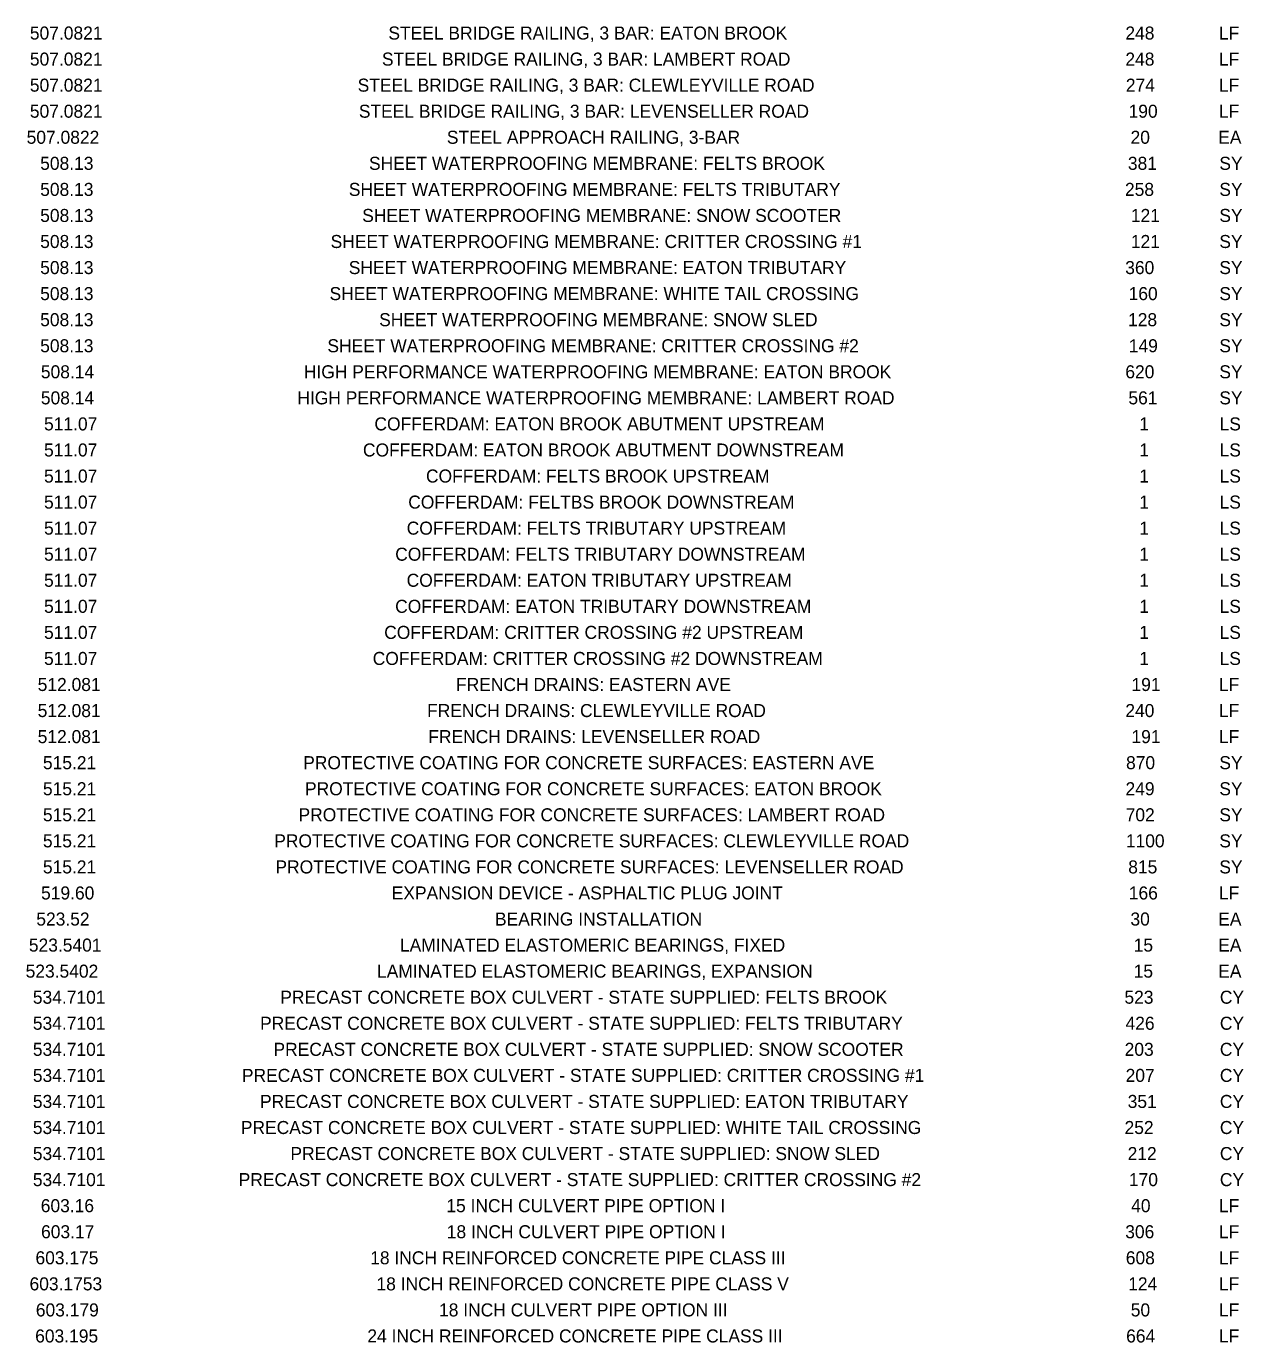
# Model space of a CAD drawing. Extents: x -18.7 to 5.6, y -2.7 to 4.
# Drawn here: x -18.677 to -17.757, y 1.164 to 2.159 of the extents above; entities that cross this region are included whole.
import ezdxf

# ---------------------------------------------------------------- set-up
doc = ezdxf.new("R2010")
doc.units = 0
doc.layers.add('ANNOTATION', color=7, linetype='Continuous')

msp = doc.modelspace()

# ---------------------------------------------------------------- texts
at = {"layer": 'ANNOTATION'}
for s, height, p in [('507.0821', 0.009843, (-18.674, 2.14859)), ('STEEL BRIDGE RAILING, 3 BAR: EATON BROOK', 0.009843, (-18.40311, 2.14859)), ('248', 0.009843, (-17.84626, 2.14859)), ('LF', 0.009843, (-17.77549, 2.14859)), ('507.0821', 0.009843, (-18.674, 2.1289)), ('STEEL BRIDGE RAILING, 3 BAR: LAMBERT ROAD', 0.009843, (-18.408, 2.1289)), ('248', 0.009843, (-17.84626, 2.1289)), ('LF', 0.009843, (-17.77549, 2.1289)), ('507.0821', 0.009843, (-18.674, 2.10921)), ('STEEL BRIDGE RAILING, 3 BAR: CLEWLEYVILLE ROAD', 0.009843, (-18.42633, 2.10921)), ('274', 0.009843, (-17.84592, 2.10921)), ('LF', 0.009843, (-17.77549, 2.10921)), ('507.0821', 0.009843, (-18.674, 2.08953)), ('STEEL BRIDGE RAILING, 3 BAR: LEVENSELLER ROAD', 0.009843, (-18.42543, 2.08953)), ('190', 0.009843, (-17.84382, 2.08953)), ('LF', 0.009843, (-17.77549, 2.08953)), ('507.0822', 0.009843, (-18.67644, 2.06984)), ('STEEL APPROACH RAILING, 3-BAR', 0.009843, (-18.35896, 2.06984)), ('20', 0.009843, (-17.84235, 2.06984)), ('EA', 0.009843, (-17.77611, 2.06984)), ('508.13', 0.009843, (-18.66621, 2.05016)), ('SHEET WATERPROOFING MEMBRANE: FELTS BROOK', 0.009843, (-18.41775, 2.05016)), ('381', 0.009843, (-17.84436, 2.05016)), ('SY', 0.009843, (-17.77526, 2.05016)), ('508.13', 0.009843, (-18.66621, 2.03047)), ('SHEET WATERPROOFING MEMBRANE: FELTS TRIBUTARY', 0.009843, (-18.43302, 2.03047)), ('258', 0.009843, (-17.84657, 2.03047)), ('SY', 0.009843, (-17.77526, 2.03047)), ('508.13', 0.009843, (-18.66621, 2.01078)), ('SHEET WATERPROOFING MEMBRANE: SNOW SCOOTER', 0.009843, (-18.4229, 2.01078)), ('121', 0.009843, (-17.84212, 2.01078)), ('SY', 0.009843, (-17.77526, 2.01078)), ('508.13', 0.009843, (-18.66621, 1.9911)), ('SHEET WATERPROOFING MEMBRANE: CRITTER CROSSING #1', 0.009843, (-18.44676, 1.9911)), ('121', 0.009843, (-17.84212, 1.9911)), ('SY', 0.009843, (-17.77526, 1.9911)), ('508.13', 0.009843, (-18.66621, 1.97141)), ('SHEET WATERPROOFING MEMBRANE: EATON TRIBUTARY', 0.009843, (-18.43306, 1.97141)), ('360', 0.009843, (-17.84638, 1.97141)), ('SY', 0.009843, (-17.77526, 1.97141)), ('508.13', 0.009843, (-18.66621, 1.95173)), ('SHEET WATERPROOFING MEMBRANE: WHITE TAIL CROSSING', 0.009843, (-18.44756, 1.95173)), ('160', 0.009843, (-17.84382, 1.95173)), ('SY', 0.009843, (-17.77526, 1.95173)), ('508.13', 0.009843, (-18.66621, 1.93204)), ('SHEET WATERPROOFING MEMBRANE: SNOW SLED', 0.009843, (-18.41009, 1.93204)), ('128', 0.009843, (-17.84425, 1.93204)), ('SY', 0.009843, (-17.77526, 1.93204)), ('508.13', 0.009843, (-18.66621, 1.91235)), ('SHEET WATERPROOFING MEMBRANE: CRITTER CROSSING #2', 0.009843, (-18.4492, 1.91235)), ('149', 0.009843, (-17.84367, 1.91235)), ('SY', 0.009843, (-17.77526, 1.91235)), ('508.14', 0.009843, (-18.6657, 1.89267)), ('HIGH PERFORMANCE WATERPROOFING MEMBRANE: EATON BROOK', 0.009843, (-18.467, 1.89267)), ('620', 0.009843, (-17.8463, 1.89267)), ('SY', 0.009843, (-17.77526, 1.89267)), ('508.14', 0.009843, (-18.6657, 1.87298)), ('HIGH PERFORMANCE WATERPROOFING MEMBRANE: LAMBERT ROAD', 0.009843, (-18.47189, 1.87298)), ('561', 0.009843, (-17.84398, 1.87298)), ('SY', 0.009843, (-17.77526, 1.87298)), ('511.07', 0.009843, (-18.6633, 1.8533)), ('COFFERDAM: EATON BROOK ABUTMENT UPSTREAM', 0.009843, (-18.41366, 1.8533)), ('1', 0.00984, (-17.83576, 1.8533)), ('LS', 0.009843, (-17.77506, 1.8533)), ('511.07', 0.009843, (-18.6633, 1.83361)), ('COFFERDAM: EATON BROOK ABUTMENT DOWNSTREAM', 0.009843, (-18.42234, 1.83361)), ('1', 0.00984, (-17.83576, 1.83361)), ('LS', 0.009843, (-17.77506, 1.83361)), ('511.07', 0.009843, (-18.6633, 1.81392)), ('COFFERDAM: FELTS BROOK UPSTREAM', 0.009843, (-18.37471, 1.81392)), ('1', 0.00984, (-17.83576, 1.81392)), ('LS', 0.009843, (-17.77506, 1.81392)), ('511.07', 0.009843, (-18.6633, 1.79424)), ('COFFERDAM: FELTBS BROOK DOWNSTREAM', 0.009843, (-18.38812, 1.79424)), ('1', 0.00984, (-17.83576, 1.79424)), ('LS', 0.009843, (-17.77506, 1.79424)), ('511.07', 0.009843, (-18.6633, 1.77455)), ('COFFERDAM: FELTS TRIBUTARY UPSTREAM', 0.009843, (-18.38928, 1.77455)), ('1', 0.00984, (-17.83576, 1.77455)), ('LS', 0.009843, (-17.77506, 1.77455)), ('511.07', 0.009843, (-18.6633, 1.75487)), ('COFFERDAM: FELTS TRIBUTARY DOWNSTREAM', 0.009843, (-18.39796, 1.75487)), ('1', 0.00984, (-17.83576, 1.75487)), ('LS', 0.009843, (-17.77506, 1.75487)), ('511.07', 0.009843, (-18.6633, 1.73518)), ('COFFERDAM: EATON TRIBUTARY UPSTREAM', 0.009843, (-18.38932, 1.73518)), ('1', 0.00984, (-17.83576, 1.73518)), ('LS', 0.009843, (-17.77506, 1.73518)), ('511.07', 0.009843, (-18.6633, 1.71549)), ('COFFERDAM: EATON TRIBUTARY DOWNSTREAM', 0.009843, (-18.398, 1.71549)), ('1', 0.00984, (-17.83576, 1.71549)), ('LS', 0.009843, (-17.77506, 1.71549)), ('511.07', 0.009843, (-18.6633, 1.69581)), ('COFFERDAM: CRITTER CROSSING #2 UPSTREAM', 0.009843, (-18.40627, 1.69581)), ('1', 0.00984, (-17.83576, 1.69581)), ('LS', 0.009843, (-17.77506, 1.69581)), ('511.07', 0.009843, (-18.6633, 1.67612)), ('COFFERDAM: CRITTER CROSSING #2 DOWNSTREAM', 0.009843, (-18.41496, 1.67612)), ('1', 0.00984, (-17.83576, 1.67612)), ('LS', 0.009843, (-17.77506, 1.67612)), ('512.081', 0.009843, (-18.6681, 1.65644)), ('FRENCH DRAINS: EASTERN AVE', 0.009843, (-18.35201, 1.65644)), ('191', 0.009843, (-17.84165, 1.65644)), ('LF', 0.009843, (-17.77549, 1.65644)), ('512.081', 0.009843, (-18.6681, 1.63675)), ('FRENCH DRAINS: CLEWLEYVILLE ROAD', 0.009843, (-18.37387, 1.63675)), ('240', 0.009843, (-17.8463, 1.63675)), ('LF', 0.009843, (-17.77549, 1.63675)), ('512.081', 0.009843, (-18.6681, 1.61706)), ('FRENCH DRAINS: LEVENSELLER ROAD', 0.009843, (-18.37297, 1.61706)), ('191', 0.009843, (-17.84165, 1.61706)), ('LF', 0.009843, (-17.77549, 1.61706)), ('515.21', 0.009843, (-18.66415, 1.59738)), ('PROTECTIVE COATING FOR CONCRETE SURFACES: EASTERN AVE', 0.009843, (-18.46749, 1.59738)), ('870', 0.009843, (-17.84576, 1.59738)), ('SY', 0.009843, (-17.77526, 1.59738)), ('515.21', 0.009843, (-18.66415, 1.57769)), ('PROTECTIVE COATING FOR CONCRETE SURFACES: EATON BROOK', 0.009843, (-18.46613, 1.57769)), ('249', 0.009843, (-17.84615, 1.57769)), ('SY', 0.009843, (-17.77526, 1.57769)), ('515.21', 0.009843, (-18.66415, 1.55801)), ('PROTECTIVE COATING FOR CONCRETE SURFACES: LAMBERT ROAD', 0.009843, (-18.47102, 1.55801)), ('702', 0.009843, (-17.84603, 1.55801)), ('SY', 0.009843, (-17.77526, 1.55801)), ('515.21', 0.009843, (-18.66415, 1.53832)), ('PROTECTIVE COATING FOR CONCRETE SURFACES: CLEWLEYVILLE ROAD', 0.009843, (-18.48935, 1.53832)), ('1100', 0.009843, (-17.84591, 1.53832)), ('SY', 0.009843, (-17.77526, 1.53832)), ('515.21', 0.009843, (-18.66415, 1.51863)), ('PROTECTIVE COATING FOR CONCRETE SURFACES: LEVENSELLER ROAD', 0.009843, (-18.48845, 1.51863)), ('815', 0.009843, (-17.84409, 1.51863)), ('SY', 0.009843, (-17.77526, 1.51863)), ('519.60', 0.009843, (-18.66555, 1.49895)), ('EXPANSION DEVICE - ASPHALTIC PLUG JOINT', 0.009843, (-18.4006, 1.49895)), ('166', 0.009843, (-17.84367, 1.49895)), ('LF', 0.009843, (-17.77549, 1.49895)), ('523.52', 0.009843, (-18.66915, 1.47926)), ('BEARING INSTALLATION', 0.009843, (-18.32257, 1.47926)), ('30', 0.009843, (-17.84243, 1.47926)), ('EA', 0.009843, (-17.77611, 1.47926)), ('523.5401', 0.009843, (-18.67477, 1.45958)), ('LAMINATED ELASTOMERIC BEARINGS, FIXED', 0.009843, (-18.39438, 1.45958)), ('15', 0.009843, (-17.83999, 1.45958)), ('EA', 0.009843, (-17.77611, 1.45958)), ('523.5402', 0.009843, (-18.67721, 1.43989)), ('LAMINATED ELASTOMERIC BEARINGS, EXPANSION', 0.009843, (-18.4117, 1.43989)), ('15', 0.009843, (-17.83999, 1.43989)), ('EA', 0.009843, (-17.77611, 1.43989)), ('534.7101', 0.009843, (-18.67175, 1.4202)), ('PRECAST CONCRETE BOX CULVERT - STATE SUPPLIED: FELTS BROOK', 0.009843, (-18.4848, 1.4202)), ('523', 0.009843, (-17.84696, 1.4202)), ('CY', 0.009843, (-17.77487, 1.4202)), ('534.7101', 0.009843, (-18.67175, 1.40052)), ('PRECAST CONCRETE BOX CULVERT - STATE SUPPLIED: FELTS TRIBUTARY', 0.009843, (-18.50006, 1.40052)), ('426', 0.009843, (-17.84615, 1.40052)), ('CY', 0.009843, (-17.77487, 1.40052)), ('534.7101', 0.009843, (-18.67175, 1.38083)), ('PRECAST CONCRETE BOX CULVERT - STATE SUPPLIED: SNOW SCOOTER', 0.009843, (-18.48995, 1.38083)), ('203', 0.009843, (-17.84681, 1.38083)), ('CY', 0.009843, (-17.77487, 1.38083)), ('534.7101', 0.009843, (-18.67175, 1.36115)), ('PRECAST CONCRETE BOX CULVERT - STATE SUPPLIED: CRITTER CROSSING #1', 0.009843, (-18.51381, 1.36115)), ('207', 0.009843, (-17.84607, 1.36115)), ('CY', 0.009843, (-17.77487, 1.36115)), ('534.7101', 0.009843, (-18.67175, 1.34146)), ('PRECAST CONCRETE BOX CULVERT - STATE SUPPLIED: EATON TRIBUTARY', 0.009843, (-18.50011, 1.34146)), ('351', 0.009843, (-17.84452, 1.34146)), ('CY', 0.009843, (-17.77487, 1.34146)), ('534.7101', 0.009843, (-18.67175, 1.32177)), ('PRECAST CONCRETE BOX CULVERT - STATE SUPPLIED: WHITE TAIL CROSSING', 0.009843, (-18.5146, 1.32177)), ('252', 0.009843, (-17.84688, 1.32177)), ('CY', 0.009843, (-17.77487, 1.32177)), ('534.7101', 0.009843, (-18.67175, 1.30209)), ('PRECAST CONCRETE BOX CULVERT - STATE SUPPLIED: SNOW SLED', 0.009843, (-18.47714, 1.30209)), ('212', 0.009843, (-17.84456, 1.30209)), ('CY', 0.009843, (-17.77487, 1.30209)), ('534.7101', 0.009843, (-18.67175, 1.2824)), ('PRECAST CONCRETE BOX CULVERT - STATE SUPPLIED: CRITTER CROSSING #2', 0.009843, (-18.51625, 1.2824)), ('170', 0.009843, (-17.84359, 1.2824)), ('CY', 0.009843, (-17.77487, 1.2824)), ('603.16', 0.009843, (-18.66578, 1.26272)), ('15 INCH CULVERT PIPE OPTION I', 0.009843, (-18.35932, 1.26272)), ('40', 0.009843, (-17.84189, 1.26272)), ('LF', 0.009843, (-17.77549, 1.26272)), ('603.17', 0.009843, (-18.66555, 1.24303)), ('18 INCH CULVERT PIPE OPTION I', 0.009843, (-18.35901, 1.24303)), ('306', 0.009843, (-17.84638, 1.24303)), ('LF', 0.009843, (-17.77549, 1.24303)), ('603.175', 0.009843, (-18.66977, 1.22334)), ('18 INCH REINFORCED CONCRETE PIPE CLASS III', 0.009843, (-18.41684, 1.22334)), ('608', 0.009843, (-17.84595, 1.22334)), ('LF', 0.009843, (-17.77549, 1.22334)), ('603.1753', 0.009843, (-18.67426, 1.20366)), ('18 INCH REINFORCED CONCRETE PIPE CLASS V', 0.009843, (-18.41211, 1.20366)), ('124', 0.009843, (-17.84413, 1.20366)), ('LF', 0.009843, (-17.77549, 1.20366)), ('603.179', 0.009843, (-18.6695, 1.18397)), ('18 INCH CULVERT PIPE OPTION III', 0.009843, (-18.36485, 1.18397)), ('50', 0.009843, (-17.8422, 1.18397)), ('LF', 0.009843, (-17.77549, 1.18397)), ('603.195', 0.009843, (-18.67, 1.16429)), ('24 INCH REINFORCED CONCRETE PIPE CLASS III', 0.009843, (-18.41901, 1.16429)), ('664', 0.009843, (-17.84568, 1.16429)), ('LF', 0.009843, (-17.77549, 1.16429))]:
    msp.add_text(s, height=height, dxfattribs=at).set_placement(p)

doc.saveas('drawing.dxf')
